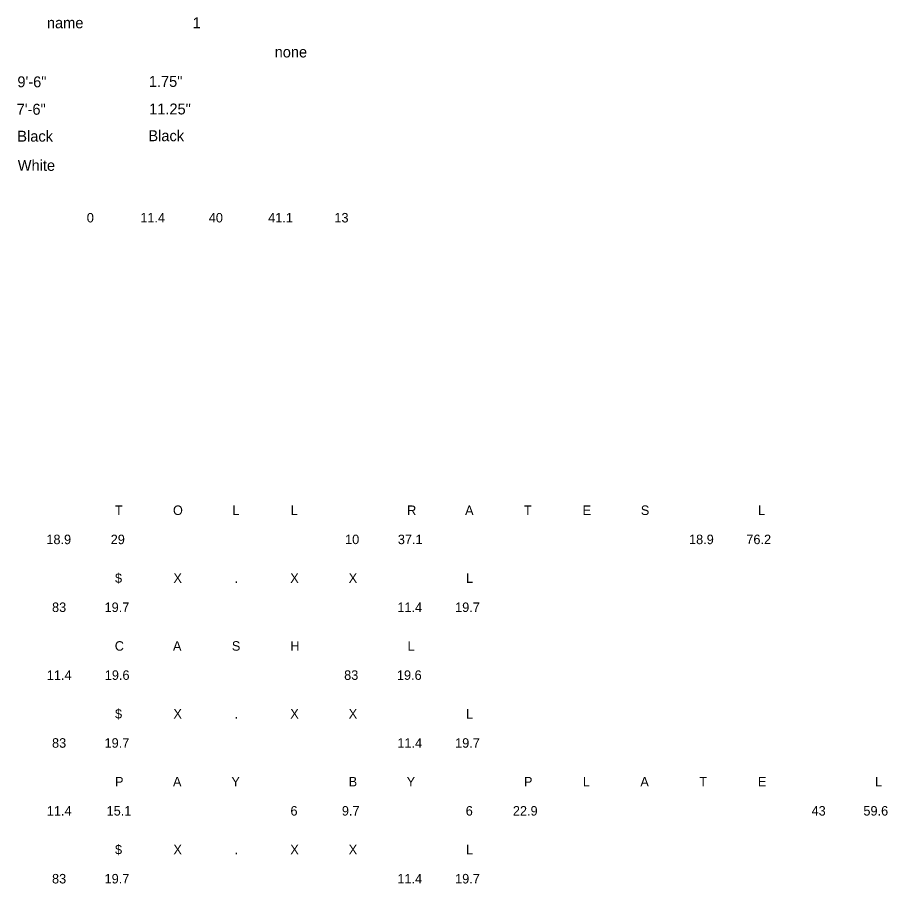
# Model space of a CAD drawing. Extents: x 10268195 to 10268685, y 2140733 to 2142689.
# Drawn here: x 10268655.16 to 10268685.42, y 2142495.94 to 2142526.06 of the extents above; entities that cross this region are included whole.
import ezdxf

# ---------------------------------------------------------------- set-up
doc = ezdxf.new("R2010")
doc.units = 0
doc.layers.add('GSSign', color=7, linetype='Continuous')

msp = doc.modelspace()

# ---------------------------------------------------------------- texts
at = {"layer": 'GSSign'}
for s, height, p in [('name', 0.3796, (10268656.182, 2142525.68)), ('1', 0.38, (10268661.25, 2142525.679)), ('none', 0.3796, (10268664.103, 2142524.666)), ('9\'-6"', 0.3796, (10268655.155, 2142523.628)), ('1.75"', 0.3796, (10268659.727, 2142523.642)), ('7\'-6"', 0.3796, (10268655.13, 2142522.674)), ('11.25"', 0.3796, (10268659.737, 2142522.684)), ('Black', 0.3796, (10268655.151, 2142521.738)), ('Black', 0.3796, (10268659.711, 2142521.753)), ('White', 0.3796, (10268655.168, 2142520.723)), ('0', 0.331, (10268657.569, 2142518.927)), ('11.4', 0.3309, (10268659.43, 2142518.927)), ('40', 0.3309, (10268661.811, 2142518.927)), ('41.1', 0.3309, (10268663.877, 2142518.927)), ('13', 0.3309, (10268666.18, 2142518.927)), ('T', 0.331, (10268658.55, 2142508.754)), ('O', 0.331, (10268660.566, 2142508.754)), ('L', 0.331, (10268662.629, 2142508.754)), ('L', 0.331, (10268664.661, 2142508.754)), ('R', 0.331, (10268668.71, 2142508.754)), ('A', 0.331, (10268670.726, 2142508.754)), ('T', 0.331, (10268672.774, 2142508.754)), ('E', 0.331, (10268674.813, 2142508.754)), ('S', 0.331, (10268676.838, 2142508.754)), ('L', 0.331, (10268680.917, 2142508.754)), ('18.9', 0.3309, (10268656.163, 2142507.74)), ('29', 0.3309, (10268658.4, 2142507.74)), ('10', 0.3309, (10268666.552, 2142507.74)), ('37.1', 0.3309, (10268668.387, 2142507.74)), ('18.9', 0.3309, (10268678.515, 2142507.74)), ('76.2', 0.3309, (10268680.508, 2142507.74)), ('$', 0.331, (10268658.55, 2142506.394)), ('X', 0.331, (10268660.582, 2142506.394)), ('X', 0.331, (10268664.646, 2142506.394)), ('X', 0.331, (10268666.678, 2142506.394)), ('L', 0.331, (10268670.757, 2142506.394)), ('.', 0.331, (10268662.708, 2142506.394)), ('83', 0.3309, (10268656.36, 2142505.38)), ('19.7', 0.3309, (10268658.187, 2142505.38)), ('11.4', 0.3309, (10268668.371, 2142505.38)), ('19.7', 0.3309, (10268670.379, 2142505.38)), ('C', 0.331, (10268658.542, 2142504.034)), ('A', 0.331, (10268660.566, 2142504.034)), ('S', 0.331, (10268662.614, 2142504.034)), ('H', 0.331, (10268664.646, 2142504.034)), ('L', 0.331, (10268668.725, 2142504.034)), ('11.4', 0.3309, (10268656.179, 2142503.02)), ('19.6', 0.3309, (10268658.195, 2142503.02)), ('83', 0.3309, (10268666.52, 2142503.02)), ('19.6', 0.3309, (10268668.355, 2142503.02)), ('$', 0.331, (10268658.55, 2142501.674)), ('X', 0.331, (10268660.582, 2142501.674)), ('X', 0.331, (10268664.646, 2142501.674)), ('X', 0.331, (10268666.678, 2142501.674)), ('L', 0.331, (10268670.757, 2142501.674)), ('.', 0.331, (10268662.708, 2142501.674)), ('83', 0.3309, (10268656.36, 2142500.66)), ('19.7', 0.3309, (10268658.187, 2142500.66)), ('11.4', 0.3309, (10268668.371, 2142500.66)), ('19.7', 0.3309, (10268670.379, 2142500.66)), ('P', 0.331, (10268658.55, 2142499.314)), ('A', 0.331, (10268660.566, 2142499.314)), ('Y', 0.331, (10268662.598, 2142499.314)), ('B', 0.331, (10268666.678, 2142499.314)), ('Y', 0.331, (10268668.694, 2142499.314)), ('P', 0.331, (10268672.774, 2142499.314)), ('L', 0.331, (10268674.821, 2142499.314)), ('A', 0.331, (10268676.822, 2142499.314)), ('T', 0.331, (10268678.87, 2142499.314)), ('E', 0.331, (10268680.909, 2142499.314)), ('L', 0.331, (10268684.981, 2142499.314)), ('11.4', 0.3309, (10268656.179, 2142498.3)), ('15.1', 0.3309, (10268658.258, 2142498.3)), ('6', 0.331, (10268664.653, 2142498.3)), ('9.7', 0.3309, (10268666.441, 2142498.3)), ('6', 0.331, (10268670.749, 2142498.3)), ('22.9', 0.3309, (10268672.388, 2142498.3)), ('43', 0.3309, (10268682.776, 2142498.3)), ('59.6', 0.3309, (10268684.58, 2142498.3)), ('$', 0.331, (10268658.55, 2142496.954)), ('X', 0.331, (10268660.582, 2142496.954)), ('X', 0.331, (10268664.646, 2142496.954)), ('X', 0.331, (10268666.678, 2142496.954)), ('L', 0.331, (10268670.757, 2142496.954)), ('.', 0.331, (10268662.708, 2142496.954)), ('83', 0.3309, (10268656.36, 2142495.94)), ('19.7', 0.3309, (10268658.187, 2142495.94)), ('11.4', 0.3309, (10268668.371, 2142495.94)), ('19.7', 0.3309, (10268670.379, 2142495.94))]:
    msp.add_text(s, height=height, dxfattribs=at).set_placement(p)

doc.saveas('drawing.dxf')
